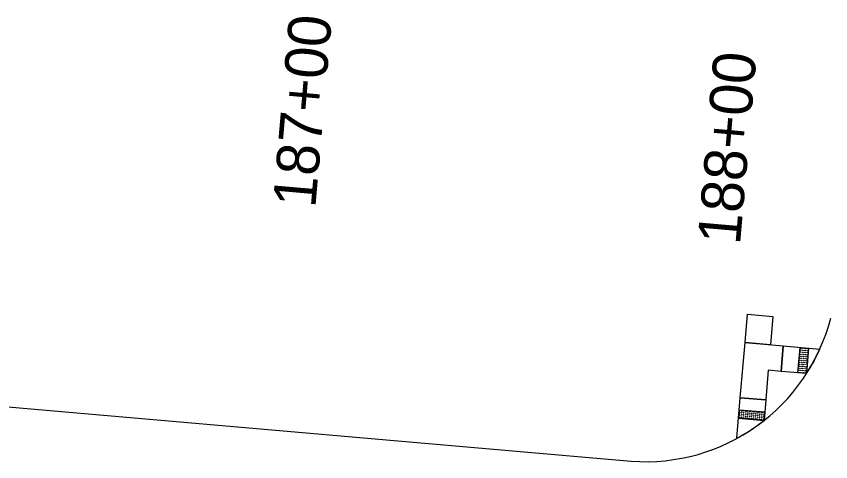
# Model space of a CAD drawing. Extents: x 20499216 to 20505321, y 7953487 to 7960535.
# Drawn here: x 20502347.4 to 20502538.4, y 7953852.7 to 7953957 of the extents above; entities that cross this region are included whole.
import ezdxf

# ---------------------------------------------------------------- set-up
doc = ezdxf.new("R2010")
doc.units = 0
for name, color, linetype in [('Drainage', 7, 'Continuous'), ('EXT_CU', 7, 'Continuous'), ('EXT_RR', 7, 'Continuous'), ('NamedBoundary', 7, 'Continuous'), ('Roadways', 7, 'Continuous')]:
    doc.layers.add(name, color=color, linetype=linetype)

msp = doc.modelspace()

# ---------------------------------------------------------------- linework, layer by layer
at = {"layer": 'Drainage'}
for points in [[(20502518.94, 7953887.24), (20502524.88, 7953886.71), (20502524.31, 7953880.09), (20502518.36, 7953880.61)], [(20502516.81, 7953862.88), (20502517.23, 7953867.69), (20502523.2, 7953867.17), (20502522.79, 7953862.36)]]:
    msp.add_lwpolyline(points, close=True, dxfattribs=at)
for points in [[(20502532.73, 7953873.34), (20502526.78, 7953873.85), (20502527.3, 7953879.83), (20502535.86, 7953879.09)], [(20502516.5, 7953858.25), (20502516.41, 7953858.26), (20502516.81, 7953862.87), (20502522.79, 7953862.35)]]:
    msp.add_lwpolyline(points, dxfattribs=at)
for centre, radius, start, end in [((20502505.15, 7953892.12), 33.37, 325.7443, 337.0087), ((20502495.51, 7953897.35), 44.38, 302.7521, 307.9436), ((20502495.51, 7953897.35), 44.37, 298.2339, 302.7521)]:
    msp.add_arc(centre, radius, start, end, dxfattribs=at)
at = {"layer": 'EXT_CU'}
for p, q in [((20502530.73, 7953873.51), (20502531.26, 7953879.49)), ((20502531.26, 7953879.49), (20502533.25, 7953879.31)), ((20502533.25, 7953879.31), (20502532.73, 7953873.34)), ((20502532.73, 7953873.34), (20502530.73, 7953873.51)), ((20502516.81, 7953862.87), (20502516.99, 7953864.87)), ((20502516.99, 7953864.87), (20502522.97, 7953864.35)), ((20502522.97, 7953864.35), (20502522.79, 7953862.36)), ((20502522.79, 7953862.36), (20502516.81, 7953862.87))]:
    msp.add_line(p, q, dxfattribs=at)
for centre, major_axis in [((20502531.37, 7953878.37), (0.0038, 0.0448)), ((20502531.37, 7953878.37), (0.0019, 0.0224)), ((20502531.41, 7953878.84), (0.0038, 0.0448)), ((20502531.41, 7953878.84), (0.0019, 0.0224)), ((20502531.45, 7953879.31), (0.0038, 0.0448)), ((20502531.45, 7953879.31), (0.0019, 0.0224)), ((20502531.76, 7953878.34), (0.0038, 0.0448)), ((20502531.76, 7953878.34), (0.0019, 0.0224)), ((20502531.8, 7953878.8), (0.0038, 0.0448)), ((20502531.8, 7953878.8), (0.0019, 0.0224)), ((20502531.84, 7953879.27), (0.0038, 0.0448)), ((20502531.84, 7953879.27), (0.0019, 0.0224)), ((20502532.15, 7953878.3), (0.0038, 0.0448)), ((20502532.15, 7953878.3), (0.0019, 0.0224)), ((20502532.19, 7953878.77), (0.0038, 0.0448)), ((20502532.19, 7953878.77), (0.0019, 0.0224)), ((20502532.23, 7953879.24), (0.0038, 0.0448)), ((20502532.23, 7953879.24), (0.0019, 0.0224)), ((20502532.54, 7953878.27), (0.0038, 0.0448)), ((20502532.58, 7953878.73), (0.0038, 0.0448)), ((20502532.58, 7953878.73), (0.0019, 0.0224)), ((20502532.62, 7953879.2), (0.0038, 0.0448)), ((20502532.62, 7953879.2), (0.0019, 0.0224)), ((20502532.97, 7953878.7), (0.0038, 0.0448)), ((20502532.97, 7953878.7), (0.0019, 0.0224)), ((20502533.01, 7953879.17), (0.0038, 0.0448)), ((20502533.01, 7953879.17), (0.0019, 0.0224)), ((20502531.2, 7953876.47), (0.0038, 0.0448)), ((20502531.2, 7953876.47), (0.0019, 0.0224)), ((20502531.25, 7953876.94), (0.0038, 0.0448)), ((20502531.25, 7953876.94), (0.0019, 0.0224)), ((20502531.29, 7953877.41), (0.0038, 0.0448)), ((20502531.29, 7953877.41), (0.0019, 0.0224)), ((20502531.33, 7953877.88), (0.0038, 0.0448)), ((20502531.33, 7953877.88), (0.0019, 0.0224)), ((20502531.59, 7953876.44), (0.0038, 0.0448)), ((20502531.59, 7953876.44), (0.0019, 0.0224)), ((20502531.64, 7953876.91), (0.0038, 0.0448)), ((20502531.64, 7953876.91), (0.0019, 0.0224)), ((20502531.68, 7953877.37), (0.0038, 0.0448)), ((20502531.68, 7953877.37), (0.0019, 0.0224)), ((20502531.72, 7953877.84), (0.0038, 0.0448)), ((20502531.72, 7953877.84), (0.0019, 0.0224)), ((20502531.98, 7953876.4), (0.0038, 0.0448)), ((20502531.98, 7953876.4), (0.0019, 0.0224)), ((20502532.03, 7953876.87), (0.0038, 0.0448)), ((20502532.03, 7953876.87), (0.0019, 0.0224)), ((20502532.07, 7953877.34), (0.0038, 0.0448)), ((20502532.07, 7953877.34), (0.0019, 0.0224)), ((20502532.11, 7953877.81), (0.0038, 0.0448)), ((20502532.11, 7953877.81), (0.0019, 0.0224)), ((20502532.37, 7953876.37), (0.0038, 0.0448)), ((20502532.42, 7953876.84), (0.0038, 0.0448)), ((20502532.42, 7953876.84), (0.0019, 0.0224)), ((20502532.46, 7953877.3), (0.0038, 0.0448)), ((20502532.46, 7953877.3), (0.0019, 0.0224)), ((20502532.5, 7953877.77), (0.0038, 0.0448)), ((20502532.5, 7953877.77), (0.0019, 0.0224)), ((20502532.54, 7953878.27), (0.0019, 0.0224)), ((20502532.81, 7953876.8), (0.0038, 0.0448)), ((20502532.81, 7953876.8), (0.0019, 0.0224)), ((20502532.85, 7953877.27), (0.0038, 0.0448)), ((20502532.85, 7953877.27), (0.0019, 0.0224)), ((20502532.89, 7953877.74), (0.0038, 0.0448)), ((20502532.89, 7953877.74), (0.0019, 0.0224)), ((20502532.93, 7953878.23), (0.0038, 0.0448)), ((20502532.93, 7953878.23), (0.0019, 0.0224)), ((20502531.04, 7953874.6), (0.0038, 0.0448)), ((20502531.04, 7953874.6), (0.0019, 0.0224)), ((20502531.08, 7953875.07), (0.0038, 0.0448)), ((20502531.08, 7953875.07), (0.0019, 0.0224)), ((20502531.12, 7953875.54), (0.0038, 0.0448)), ((20502531.12, 7953875.54), (0.0019, 0.0224)), ((20502531.16, 7953876), (0.0038, 0.0448)), ((20502531.16, 7953876), (0.0019, 0.0224)), ((20502531.43, 7953874.56), (0.0038, 0.0448)), ((20502531.43, 7953874.56), (0.0019, 0.0224)), ((20502531.47, 7953875.03), (0.0038, 0.0448)), ((20502531.47, 7953875.03), (0.0019, 0.0224)), ((20502531.51, 7953875.5), (0.0038, 0.0448)), ((20502531.51, 7953875.5), (0.0019, 0.0224)), ((20502531.55, 7953875.97), (0.0038, 0.0448)), ((20502531.55, 7953875.97), (0.0019, 0.0224)), ((20502531.82, 7953874.53), (0.0038, 0.0448)), ((20502531.82, 7953874.53), (0.0019, 0.0224)), ((20502531.86, 7953875), (0.0038, 0.0448)), ((20502531.86, 7953875), (0.0019, 0.0224)), ((20502531.9, 7953875.47), (0.0038, 0.0448)), ((20502531.9, 7953875.47), (0.0019, 0.0224)), ((20502531.94, 7953875.93), (0.0038, 0.0448)), ((20502531.94, 7953875.93), (0.0019, 0.0224)), ((20502532.21, 7953874.5), (0.0038, 0.0448)), ((20502532.21, 7953874.5), (0.0019, 0.0224)), ((20502532.25, 7953874.96), (0.0038, 0.0448)), ((20502532.25, 7953874.96), (0.0019, 0.0224)), ((20502532.29, 7953875.43), (0.0038, 0.0448)), ((20502532.29, 7953875.43), (0.0019, 0.0224)), ((20502532.33, 7953875.9), (0.0038, 0.0448)), ((20502532.33, 7953875.9), (0.0019, 0.0224)), ((20502532.37, 7953876.37), (0.0019, 0.0224)), ((20502532.6, 7953874.46), (0.0038, 0.0448)), ((20502532.64, 7953874.93), (0.0038, 0.0448)), ((20502532.64, 7953874.93), (0.0019, 0.0224)), ((20502532.68, 7953875.4), (0.0038, 0.0448)), ((20502532.68, 7953875.4), (0.0019, 0.0224)), ((20502532.72, 7953875.87), (0.0038, 0.0448)), ((20502532.72, 7953875.87), (0.0019, 0.0224)), ((20502532.77, 7953876.33), (0.0038, 0.0448)), ((20502532.77, 7953876.33), (0.0019, 0.0224)), ((20502530.96, 7953873.66), (0.0038, 0.0448)), ((20502530.96, 7953873.66), (0.0019, 0.0224)), ((20502531, 7953874.13), (0.0038, 0.0448)), ((20502531, 7953874.13), (0.0019, 0.0224)), ((20502531.35, 7953873.63), (0.0038, 0.0448)), ((20502531.35, 7953873.63), (0.0019, 0.0224)), ((20502531.39, 7953874.1), (0.0038, 0.0448)), ((20502531.39, 7953874.1), (0.0019, 0.0224)), ((20502531.74, 7953873.59), (0.0038, 0.0448)), ((20502531.74, 7953873.59), (0.0019, 0.0224)), ((20502531.78, 7953874.06), (0.0038, 0.0448)), ((20502531.78, 7953874.06), (0.0019, 0.0224)), ((20502532.13, 7953873.56), (0.0038, 0.0448)), ((20502532.13, 7953873.56), (0.0019, 0.0224)), ((20502532.17, 7953874.03), (0.0038, 0.0448)), ((20502532.17, 7953874.03), (0.0019, 0.0224)), ((20502532.52, 7953873.53), (0.0038, 0.0448)), ((20502532.52, 7953873.53), (0.0019, 0.0224)), ((20502532.56, 7953873.99), (0.0038, 0.0448)), ((20502532.56, 7953873.99), (0.0019, 0.0224)), ((20502532.6, 7953874.46), (0.0019, 0.0224)), ((20502517, 7953863.07), (-0.0448, 0.0037)), ((20502517, 7953863.07), (-0.0224, 0.0019)), ((20502517.03, 7953863.46), (-0.0448, 0.0037)), ((20502517.03, 7953863.46), (-0.0224, 0.0019)), ((20502517.07, 7953863.85), (-0.0448, 0.0037)), ((20502517.07, 7953863.85), (-0.0224, 0.0019)), ((20502517.1, 7953864.24), (-0.0448, 0.0037)), ((20502517.1, 7953864.24), (-0.0224, 0.0019)), ((20502517.13, 7953864.63), (-0.0448, 0.0037)), ((20502517.13, 7953864.63), (-0.0224, 0.0019)), ((20502517.47, 7953863.03), (-0.0448, 0.0037)), ((20502517.47, 7953863.03), (-0.0224, 0.0019)), ((20502517.5, 7953863.42), (-0.0448, 0.0037)), ((20502517.5, 7953863.42), (-0.0224, 0.0019)), ((20502517.53, 7953863.81), (-0.0448, 0.0037)), ((20502517.53, 7953863.81), (-0.0224, 0.0019)), ((20502517.57, 7953864.2), (-0.0448, 0.0037)), ((20502517.57, 7953864.2), (-0.0224, 0.0019)), ((20502517.6, 7953864.59), (-0.0448, 0.0037)), ((20502517.6, 7953864.59), (-0.0224, 0.0019)), ((20502517.93, 7953862.99), (-0.0448, 0.0037)), ((20502517.97, 7953863.38), (-0.0448, 0.0037)), ((20502517.97, 7953863.38), (-0.0224, 0.0019)), ((20502518, 7953863.77), (-0.0448, 0.0037)), ((20502518, 7953863.77), (-0.0224, 0.0019)), ((20502518.04, 7953864.16), (-0.0448, 0.0037)), ((20502518.04, 7953864.16), (-0.0224, 0.0019)), ((20502518.07, 7953864.55), (-0.0448, 0.0037)), ((20502518.07, 7953864.55), (-0.0224, 0.0019)), ((20502518.46, 7953863.34), (-0.0448, 0.0037)), ((20502518.46, 7953863.34), (-0.0224, 0.0019)), ((20502518.5, 7953863.73), (-0.0448, 0.0037)), ((20502518.5, 7953863.73), (-0.0224, 0.0019)), ((20502518.53, 7953864.12), (-0.0448, 0.0037)), ((20502518.53, 7953864.12), (-0.0224, 0.0019)), ((20502518.56, 7953864.51), (-0.0448, 0.0037)), ((20502518.56, 7953864.51), (-0.0224, 0.0019)), ((20502518.93, 7953863.3), (-0.0448, 0.0037)), ((20502518.93, 7953863.3), (-0.0224, 0.0019)), ((20502518.96, 7953863.69), (-0.0448, 0.0037)), ((20502518.96, 7953863.69), (-0.0224, 0.0019)), ((20502519, 7953864.08), (-0.0448, 0.0037)), ((20502519, 7953864.08), (-0.0224, 0.0019)), ((20502519.03, 7953864.47), (-0.0448, 0.0037)), ((20502519.03, 7953864.47), (-0.0224, 0.0019)), ((20502519.4, 7953863.26), (-0.0448, 0.0037)), ((20502519.4, 7953863.26), (-0.0224, 0.0019)), ((20502519.43, 7953863.65), (-0.0448, 0.0037)), ((20502519.43, 7953863.65), (-0.0224, 0.0019)), ((20502519.47, 7953864.04), (-0.0448, 0.0037)), ((20502519.47, 7953864.04), (-0.0224, 0.0019)), ((20502519.5, 7953864.43), (-0.0448, 0.0037)), ((20502519.5, 7953864.43), (-0.0224, 0.0019)), ((20502519.87, 7953863.22), (-0.0448, 0.0037)), ((20502519.87, 7953863.22), (-0.0224, 0.0019)), ((20502519.9, 7953863.61), (-0.0448, 0.0037)), ((20502519.9, 7953863.61), (-0.0224, 0.0019)), ((20502519.93, 7953864), (-0.0448, 0.0037)), ((20502519.93, 7953864), (-0.0224, 0.0019)), ((20502519.97, 7953864.39), (-0.0448, 0.0037)), ((20502519.97, 7953864.39), (-0.0224, 0.0019)), ((20502520.33, 7953863.18), (-0.0448, 0.0037)), ((20502520.33, 7953863.18), (-0.0224, 0.0019)), ((20502520.37, 7953863.57), (-0.0448, 0.0037)), ((20502520.37, 7953863.57), (-0.0224, 0.0019)), ((20502520.4, 7953863.96), (-0.0448, 0.0037)), ((20502520.4, 7953863.96), (-0.0224, 0.0019)), ((20502520.44, 7953864.35), (-0.0448, 0.0037)), ((20502520.44, 7953864.35), (-0.0224, 0.0019)), ((20502520.8, 7953863.14), (-0.0448, 0.0037)), ((20502520.8, 7953863.14), (-0.0224, 0.0019)), ((20502520.84, 7953863.53), (-0.0448, 0.0037)), ((20502520.84, 7953863.53), (-0.0224, 0.0019)), ((20502520.87, 7953863.92), (-0.0448, 0.0037)), ((20502520.87, 7953863.92), (-0.0224, 0.0019)), ((20502520.91, 7953864.31), (-0.0448, 0.0037)), ((20502520.91, 7953864.31), (-0.0224, 0.0019)), ((20502521.27, 7953863.1), (-0.0448, 0.0037)), ((20502521.27, 7953863.1), (-0.0224, 0.0019)), ((20502521.31, 7953863.49), (-0.0448, 0.0037)), ((20502521.31, 7953863.49), (-0.0224, 0.0019)), ((20502521.34, 7953863.88), (-0.0448, 0.0037)), ((20502521.34, 7953863.88), (-0.0224, 0.0019)), ((20502521.37, 7953864.27), (-0.0448, 0.0037)), ((20502521.37, 7953864.27), (-0.0224, 0.0019)), ((20502521.74, 7953863.05), (-0.0448, 0.0037)), ((20502521.74, 7953863.05), (-0.0224, 0.0019)), ((20502521.77, 7953863.44), (-0.0448, 0.0037)), ((20502521.77, 7953863.44), (-0.0224, 0.0019)), ((20502521.81, 7953863.83), (-0.0448, 0.0037)), ((20502521.81, 7953863.83), (-0.0224, 0.0019)), ((20502521.84, 7953864.23), (-0.0448, 0.0037)), ((20502521.84, 7953864.23), (-0.0224, 0.0019)), ((20502522.21, 7953863.01), (-0.0448, 0.0037)), ((20502522.21, 7953863.01), (-0.0224, 0.0019)), ((20502522.24, 7953863.4), (-0.0448, 0.0037)), ((20502522.24, 7953863.4), (-0.0224, 0.0019)), ((20502522.28, 7953863.79), (-0.0448, 0.0037)), ((20502522.28, 7953863.79), (-0.0224, 0.0019)), ((20502522.31, 7953864.18), (-0.0448, 0.0037)), ((20502522.31, 7953864.18), (-0.0224, 0.0019)), ((20502522.71, 7953863.36), (-0.0448, 0.0037)), ((20502522.71, 7953863.36), (-0.0224, 0.0019)), ((20502522.74, 7953863.75), (-0.0448, 0.0037)), ((20502522.74, 7953863.75), (-0.0224, 0.0019)), ((20502522.78, 7953864.14), (-0.0448, 0.0037)), ((20502522.78, 7953864.14), (-0.0224, 0.0019)), ((20502517.93, 7953862.99), (-0.0224, 0.0019)), ((20502518.43, 7953862.95), (-0.0448, 0.0037)), ((20502518.43, 7953862.95), (-0.0224, 0.0019)), ((20502518.9, 7953862.91), (-0.0448, 0.0037)), ((20502518.9, 7953862.91), (-0.0224, 0.0019)), ((20502519.36, 7953862.87), (-0.0448, 0.0037)), ((20502519.36, 7953862.87), (-0.0224, 0.0019)), ((20502519.83, 7953862.83), (-0.0448, 0.0037)), ((20502519.83, 7953862.83), (-0.0224, 0.0019)), ((20502520.3, 7953862.79), (-0.0448, 0.0037)), ((20502520.3, 7953862.79), (-0.0224, 0.0019)), ((20502520.77, 7953862.75), (-0.0448, 0.0037)), ((20502520.77, 7953862.75), (-0.0224, 0.0019)), ((20502521.24, 7953862.7), (-0.0448, 0.0037)), ((20502521.24, 7953862.7), (-0.0224, 0.0019)), ((20502521.7, 7953862.66), (-0.0448, 0.0037)), ((20502521.7, 7953862.66), (-0.0224, 0.0019)), ((20502522.17, 7953862.62), (-0.0448, 0.0037)), ((20502522.17, 7953862.62), (-0.0224, 0.0019)), ((20502522.64, 7953862.58), (-0.0448, 0.0037)), ((20502522.64, 7953862.58), (-0.0224, 0.0019)), ((20502522.68, 7953862.97), (-0.0448, 0.0037)), ((20502522.68, 7953862.97), (-0.0224, 0.0019))]:
    msp.add_ellipse(centre, major_axis=major_axis, ratio=0.833333, dxfattribs=at)
at = {"layer": 'NamedBoundary'}
msp.add_lwpolyline([(20501787.19, 7953915.21), (20502204.56, 7953877.83), (20502491.63, 7953852.83)], dxfattribs=at)
msp.add_arc((20502494.97, 7953897.61), 44.91, 265.731, 345.4565, dxfattribs=at)
at = {"layer": 'Roadways'}
msp.add_lwpolyline([(20502527.3, 7953879.83), (20502526.78, 7953873.85), (20502523.8, 7953874.11), (20502523.2, 7953867.17), (20502517.23, 7953867.69), (20502518.36, 7953880.61)], close=True, dxfattribs=at)

# ---------------------------------------------------------------- texts
at = {"layer": 'EXT_RR'}
for s, p in [('187+00', (20502417.53, 7953912)), ('188+00', (20502517.15, 7953903.33))]:
    msp.add_text(s, height=10.02, rotation=85.0264, dxfattribs=at).set_placement(p)

doc.saveas('drawing.dxf')
